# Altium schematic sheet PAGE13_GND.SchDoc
size 381 x 381 mm; SheetNumber: 14; SheetTotal: 28
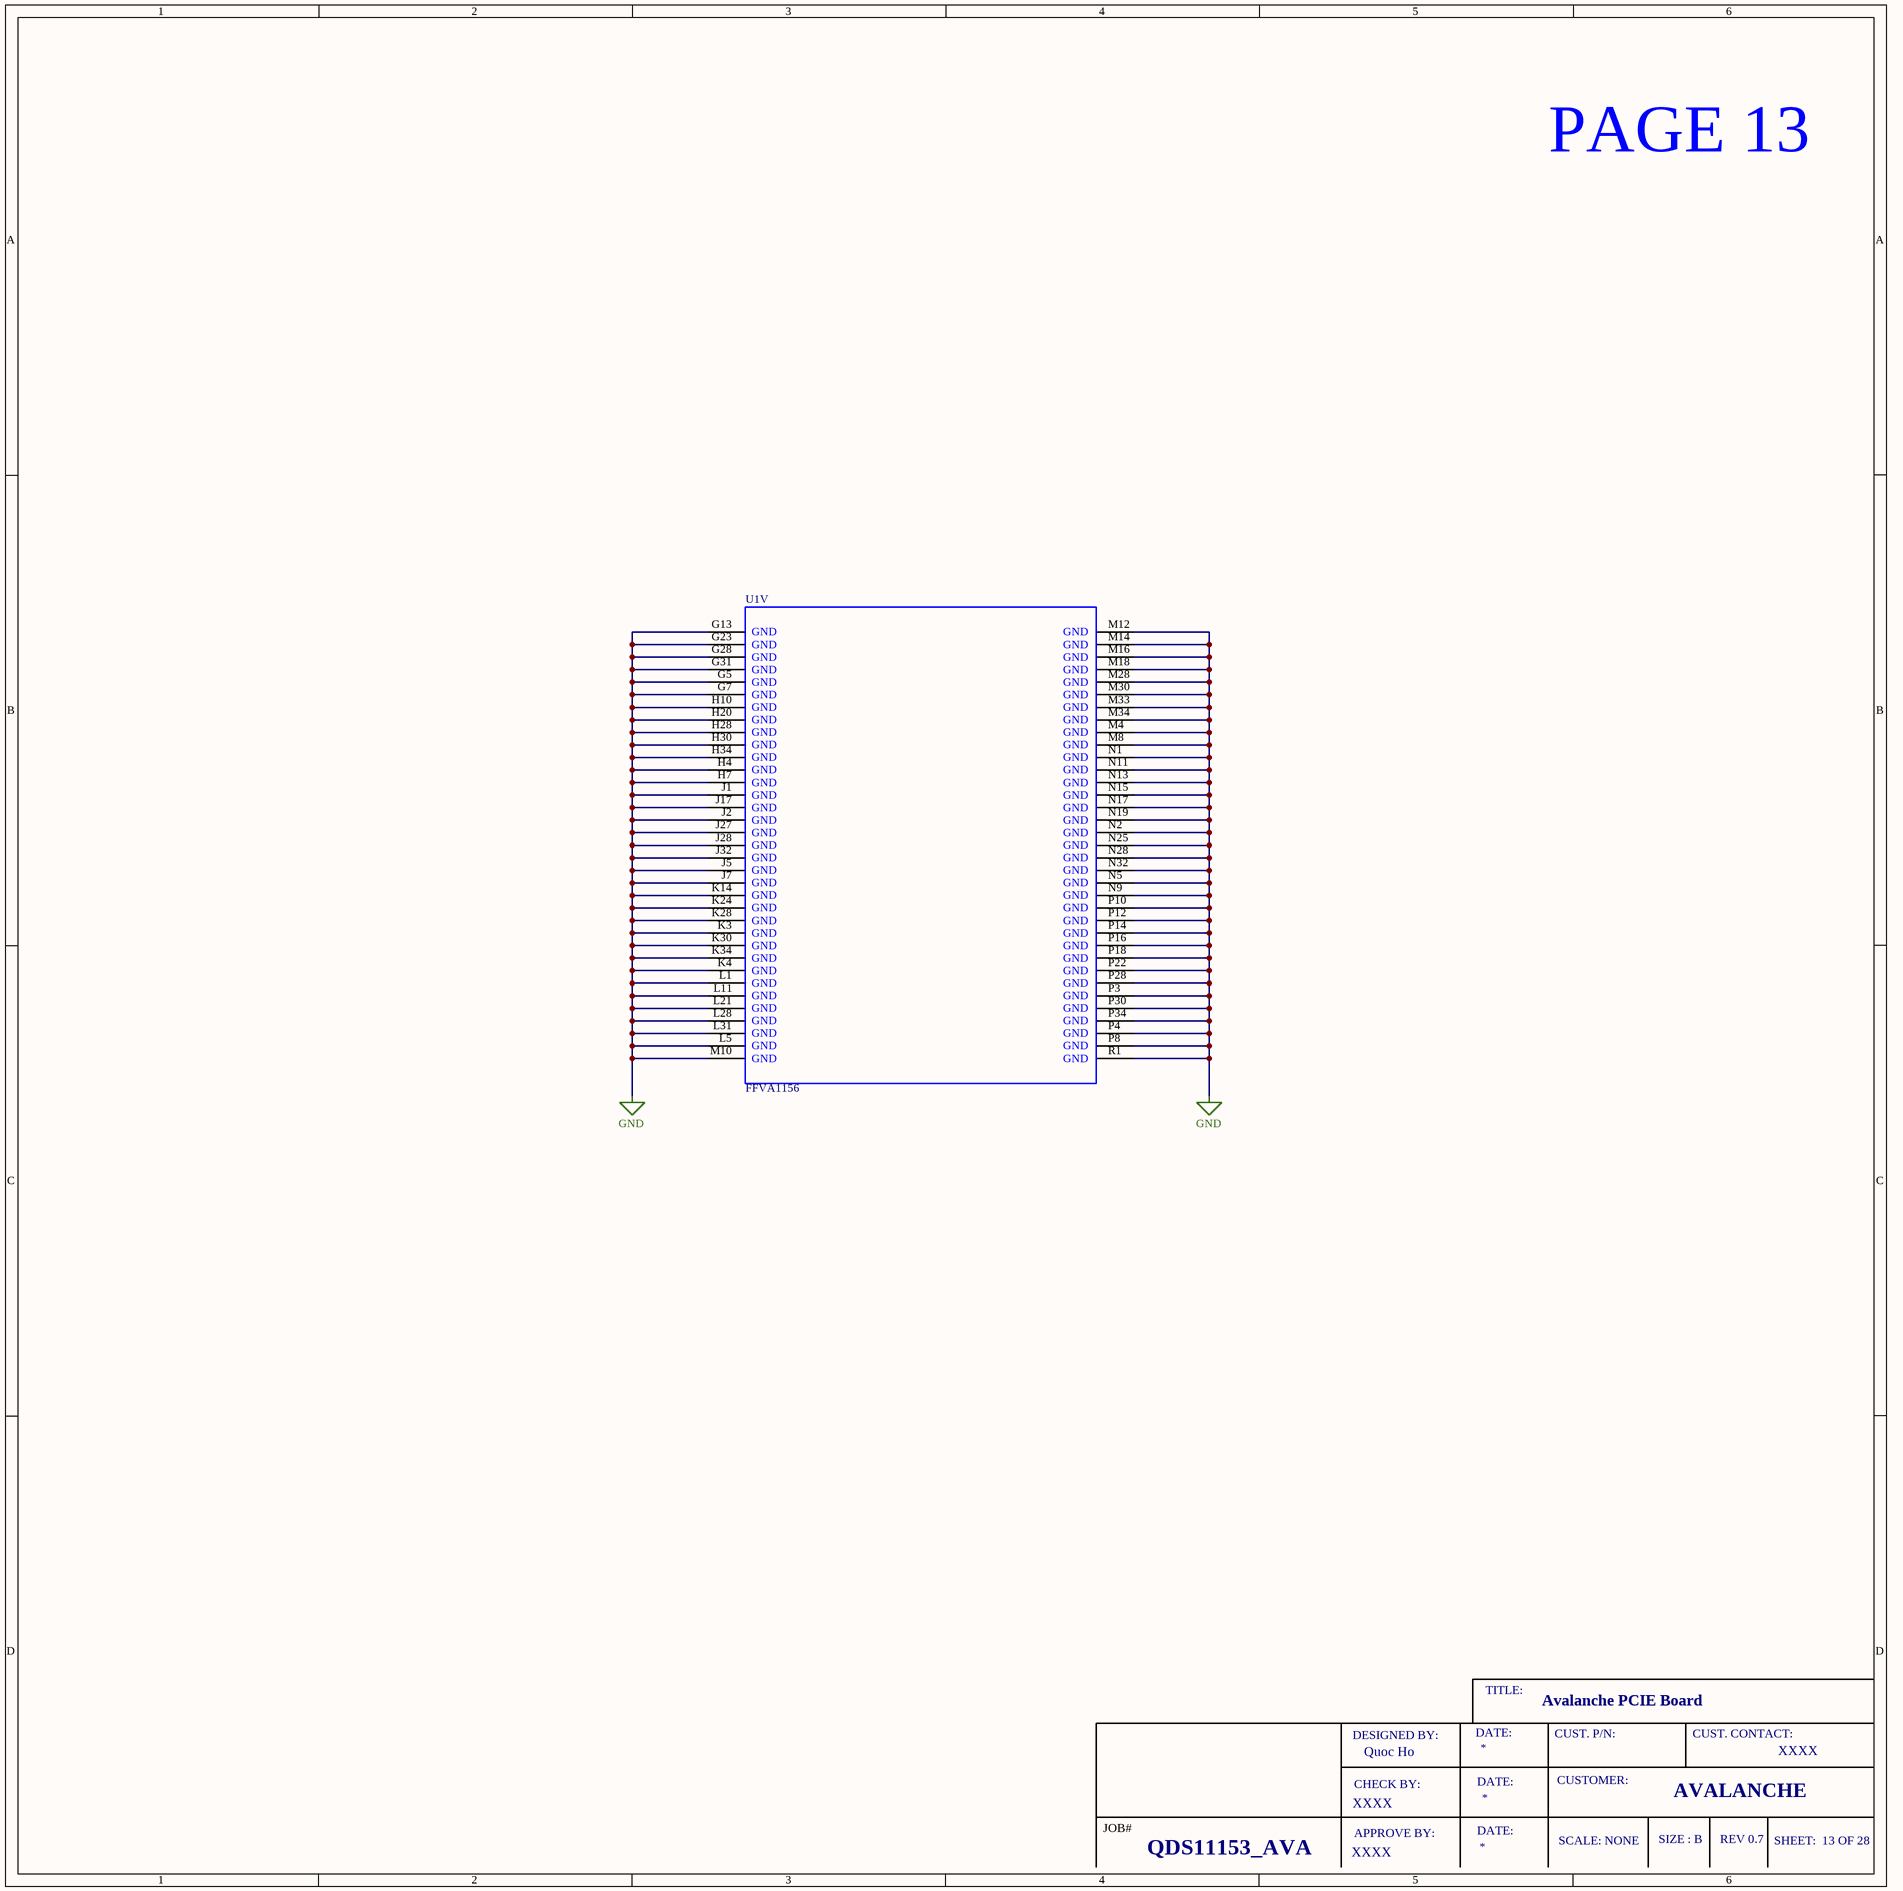
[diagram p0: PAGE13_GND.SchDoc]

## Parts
U1  FFVA1156  [FFVA1156]  (part V of 25)

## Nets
GND: U1.G5(GND) U1.G7(GND) U1.G13(GND) U1.G23(GND) U1.G28(GND) U1.G31(GND) U1.H4(GND) U1.H7(GND) U1.H10(GND) U1.H20(GND) U1.H28(GND) U1.H30(GND) U1.H34(GND) U1.J1(GND) U1.J2(GND) U1.J5(GND) U1.J7(GND) U1.J17(GND) U1.J27(GND) U1.J28(GND) U1.J32(GND) U1.K3(GND) U1.K4(GND) U1.K14(GND) U1.K24(GND) U1.K28(GND) U1.K30(GND) U1.K34(GND) U1.L1(GND) U1.L5(GND) U1.L11(GND) U1.L21(GND) U1.L28(GND) U1.L31(GND) U1.M4(GND) U1.M8(GND) U1.M10(GND) U1.M12(GND) U1.M14(GND) U1.M16(GND) U1.M18(GND) U1.M28(GND) U1.M30(GND) U1.M33(GND) U1.M34(GND) U1.N1(GND) U1.N2(GND) U1.N5(GND) U1.N9(GND) U1.N11(GND) U1.N13(GND) U1.N15(GND) U1.N17(GND) U1.N19(GND) U1.N25(GND) U1.N28(GND) U1.N32(GND) U1.P3(GND) U1.P4(GND) U1.P8(GND) U1.P10(GND) U1.P12(GND) U1.P14(GND) U1.P16(GND) U1.P18(GND) U1.P22(GND) U1.P28(GND) U1.P30(GND) U1.P34(GND) U1.R1(GND)

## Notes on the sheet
- PAGE 13
- TITLE:
- Avalanche PCIE Board
- DESIGNED BY:
- CHECK BY:
- Quoc Ho
- DATE:
- CUST. P/N:
- CUSTOMER:
- CUST. CONTACT:
- XXXX
- JOB#
- APPROVE BY:
- SCALE: NONE
- SIZE : B
- AVALANCHE
- REV 0.7
- SHEET:  13 OF 28
- QDS11153_AVA

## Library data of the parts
U1 = FFVA1156: IC FPGA 516 I/O 1156FCBGA; Manufacturer: AMD; Manufacturer Part Number: XCKU15P-1FFVA1156E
